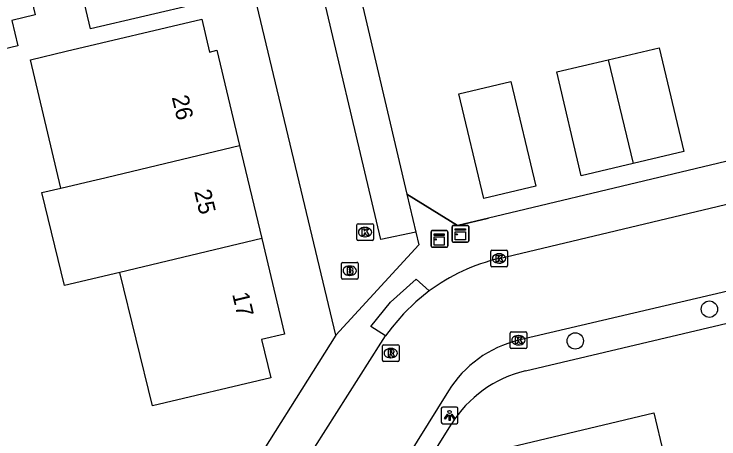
# Model space of a CAD drawing. Extents: x 158474 to 159560, y 388525 to 389605.
# Drawn here: x 159361.76 to 159403.9, y 388790.44 to 388815.87 of the extents above; entities that cross this region are included whole.
import ezdxf

# ---------------------------------------------------------------- set-up
doc = ezdxf.new("R2010")
doc.units = 0
for name, color, linetype in [('IMGEO_Boom', 7, 'Continuous'), ('IMGEO_Brandkraan', 7, 'Continuous'), ('IMGEO_Kast', 7, 'Continuous'), ('IMGEO_Kolk', 7, 'Continuous'), ('IMGEO_Lichtpunt', 7, 'Continuous'), ('IMGEO_Muur', 7, 'Continuous'), ('IMGEO_Pand', 7, 'Continuous'), ('IMGEO_Pand_nummerreeks', 7, 'Continuous'), ('IMGEO_Parkeervlak_open', 7, 'Continuous'), ('IMGEO_Rijbaan_lokaal_open', 7, 'Continuous'), ('IMGEO_Rioolput', 7, 'Continuous'), ('IMGEO_Voetpad_open', 7, 'Continuous')]:
    doc.layers.add(name, color=color, linetype=linetype)

msp = doc.modelspace()

# ---------------------------------------------------------------- linework, layer by layer
at = {"layer": 'IMGEO_Boom'}
for centre in [(159403.329, 388798.208), (159395.311, 388796.305)]:
    msp.add_circle(centre, 0.489, dxfattribs=at)
at = {"layer": 'IMGEO_Brandkraan'}
for p, q in [((159381.326, 388800.085), (159381.326, 388800.937)), ((159381.401, 388801.011), (159382.253, 388801.011)), ((159381.814, 388800.791), (159381.839, 388800.791)), ((159382.327, 388800.937), (159382.327, 388800.085)), ((159382.253, 388800.011), (159381.401, 388800.011)), ((159381.837, 388800.231), (159381.812, 388800.231))]:
    msp.add_line(p, q, dxfattribs=at)
for points in [[(159381.326, 388800.085), (159381.326, 388800.937)], [(159381.401, 388801.011), (159382.253, 388801.011)], [(159381.674, 388800.711), (159381.674, 388800.311), (159381.887, 388800.311)], [(159381.905, 388800.711), (159381.674, 388800.711)], [(159382.327, 388800.937), (159382.327, 388800.085)], [(159381.853, 388800.63), (159381.799, 388800.63), (159381.799, 388800.554)], [(159381.799, 388800.554), (159381.852, 388800.554)], [(159381.861, 388800.478), (159381.799, 388800.478), (159381.799, 388800.397)], [(159381.799, 388800.397), (159381.861, 388800.397)], [(159382.253, 388800.011), (159381.401, 388800.011)]]:
    msp.add_lwpolyline(points, dxfattribs=at)
for centre, radius, start, end in [((159381.403, 388800.935), 0.0765, 91.552, 178.448), ((159381.403, 388800.935), 0.0765, 91.552, 178.448), ((159381.909, 388800.566), 0.145, 59.4692, 91.5367), ((159382.251, 388800.935), 0.0765, 1.552, 88.448), ((159382.251, 388800.935), 0.0765, 1.552, 88.448), ((159381.854, 388800.592), 0.0379, 267.8285, 90.9355), ((159381.862, 388800.437), 0.0404, 269.8759, 90.5077), ((159381.893, 388800.562), 0.251, 268.6676, 293.5347), ((159381.934, 388800.613), 0.0922, 285.5137, 58.1501), ((159381.939, 388800.421), 0.105, 301.3115, 78.989), ((159381.403, 388800.087), 0.0765, 181.552, 268.448), ((159381.403, 388800.087), 0.0765, 181.552, 268.448), ((159382.251, 388800.087), 0.0765, 271.552, 358.448), ((159382.251, 388800.087), 0.0765, 271.552, 358.448)]:
    msp.add_arc(centre, radius, start, end, dxfattribs=at)
for centre, major_axis, ratio, start_param, end_param in [((159381.813, 388800.511), (-0.387, 0.002), 0.722429, 4.712389, 7.853982), ((159381.838, 388800.511), (-0.39, 0.002), 0.717154, 1.570796, 4.712389)]:
    msp.add_ellipse(centre, major_axis=major_axis, ratio=ratio, start_param=start_param, end_param=end_param, dxfattribs=at)
at = {"layer": 'IMGEO_Kast'}
for p, q in [((159388.02, 388803.222), (159388.861, 388803.222)), ((159388.861, 388803.222), (159388.02, 388803.222)), ((159386.687, 388801.995), (159386.687, 388802.836)), ((159386.687, 388802.836), (159386.687, 388801.995)), ((159386.762, 388802.92), (159387.603, 388802.92)), ((159387.603, 388802.92), (159386.762, 388802.92)), ((159387.687, 388802.845), (159387.687, 388802.004)), ((159387.687, 388802.004), (159387.687, 388802.845)), ((159387.945, 388802.297), (159387.945, 388803.138)), ((159387.945, 388803.138), (159387.945, 388802.297)), ((159388.945, 388803.147), (159388.945, 388802.306)), ((159388.945, 388802.306), (159388.945, 388803.147)), ((159388.87, 388802.222), (159388.029, 388802.222)), ((159388.029, 388802.222), (159388.87, 388802.222)), ((159387.612, 388801.92), (159386.771, 388801.92)), ((159386.771, 388801.92), (159387.612, 388801.92))]:
    msp.add_line(p, q, dxfattribs=at)
for points in [[(159388.14, 388803.012), (159388.74, 388803.012), (159388.74, 388802.927), (159388.14, 388802.927), (159388.14, 388803.012)], [(159388.14, 388802.837), (159388.74, 388802.837), (159388.74, 388802.348), (159388.14, 388802.348), (159388.14, 388802.837)], [(159386.882, 388802.71), (159387.482, 388802.71), (159387.482, 388802.625), (159386.882, 388802.625), (159386.882, 388802.71)], [(159386.882, 388802.535), (159387.482, 388802.535), (159387.482, 388802.046), (159386.882, 388802.046), (159386.882, 388802.535)]]:
    msp.add_lwpolyline(points, dxfattribs=at)
for centre in [(159386.966, 388802.384), (159388.224, 388802.686)]:
    msp.add_circle(centre, 0.0377, dxfattribs=at)
for centre, start, end in [((159388.023, 388803.144), 92.4484, 184.2845), ((159388.023, 388803.144), 92.4484, 184.2845), ((159388.867, 388803.144), 2.4484, 94.2845), ((159388.867, 388803.144), 2.4484, 94.2845), ((159386.765, 388802.842), 92.4484, 184.2845), ((159386.765, 388802.842), 92.4484, 184.2845), ((159387.609, 388802.842), 2.4484, 94.2845), ((159387.609, 388802.842), 2.4484, 94.2845), ((159386.765, 388801.998), 182.4484, 274.2845), ((159386.765, 388801.998), 182.4484, 274.2845), ((159387.609, 388801.998), 272.4484, 4.2845), ((159387.609, 388801.998), 272.4484, 4.2845), ((159388.023, 388802.3), 182.4484, 274.2845), ((159388.023, 388802.3), 182.4484, 274.2845), ((159388.867, 388802.3), 272.4484, 4.2845), ((159388.867, 388802.3), 272.4484, 4.2845)]:
    msp.add_arc(centre, 0.0779, start, end, dxfattribs=at)
at = {"layer": 'IMGEO_Kolk'}
for p, q in [((159382.247, 388802.397), (159382.247, 388803.249)), ((159382.322, 388803.323), (159383.174, 388803.323)), ((159383.248, 388803.249), (159383.248, 388802.397)), ((159382.735, 388803.103), (159382.76, 388803.103)), ((159382.758, 388802.543), (159382.733, 388802.543)), ((159383.174, 388802.323), (159382.322, 388802.323)), ((159390.257, 388800.815), (159390.257, 388801.667)), ((159390.332, 388801.741), (159391.184, 388801.741)), ((159391.258, 388801.667), (159391.258, 388800.815)), ((159390.745, 388801.521), (159390.77, 388801.521)), ((159391.184, 388800.741), (159390.332, 388800.741)), ((159390.768, 388800.961), (159390.743, 388800.961)), ((159391.412, 388795.919), (159391.412, 388796.771)), ((159391.487, 388796.845), (159392.339, 388796.845)), ((159391.9, 388796.625), (159391.925, 388796.625)), ((159392.413, 388796.771), (159392.413, 388795.919)), ((159391.923, 388796.065), (159391.898, 388796.065)), ((159392.339, 388795.845), (159391.487, 388795.845))]:
    msp.add_line(p, q, dxfattribs=at)
for points in [[(159382.247, 388802.397), (159382.247, 388803.249)], [(159382.322, 388803.323), (159383.174, 388803.323)], [(159383.248, 388803.249), (159383.248, 388802.397)], [(159382.568, 388803.023), (159382.691, 388803.023), (159382.691, 388802.872), (159382.821, 388803.023), (159382.985, 388803.023), (159382.839, 388802.872), (159382.992, 388802.623), (159382.84, 388802.623), (159382.755, 388802.787), (159382.691, 388802.72), (159382.691, 388802.623), (159382.568, 388802.623), (159382.568, 388803.023)], [(159383.174, 388802.323), (159382.322, 388802.323)], [(159390.257, 388800.815), (159390.257, 388801.667)], [(159390.332, 388801.741), (159391.184, 388801.741)], [(159391.258, 388801.667), (159391.258, 388800.815)], [(159390.578, 388801.441), (159390.701, 388801.441), (159390.701, 388801.29), (159390.831, 388801.441), (159390.995, 388801.441), (159390.849, 388801.29), (159391.002, 388801.041), (159390.85, 388801.041), (159390.765, 388801.205), (159390.701, 388801.138), (159390.701, 388801.041), (159390.578, 388801.041), (159390.578, 388801.441)], [(159391.184, 388800.741), (159390.332, 388800.741)], [(159391.412, 388795.919), (159391.412, 388796.771)], [(159391.487, 388796.845), (159392.339, 388796.845)], [(159391.733, 388796.545), (159391.856, 388796.545), (159391.856, 388796.394), (159391.986, 388796.545), (159392.15, 388796.545), (159392.004, 388796.394), (159392.157, 388796.145), (159392.005, 388796.145), (159391.92, 388796.309), (159391.856, 388796.242), (159391.856, 388796.145), (159391.733, 388796.145), (159391.733, 388796.545)], [(159392.413, 388796.771), (159392.413, 388795.919)], [(159392.339, 388795.845), (159391.487, 388795.845)]]:
    msp.add_lwpolyline(points, dxfattribs=at)
for centre, start, end in [((159382.324, 388803.247), 91.552, 178.448), ((159382.324, 388803.247), 91.552, 178.448), ((159383.172, 388803.247), 1.552, 88.448), ((159383.172, 388803.247), 1.552, 88.448), ((159382.324, 388802.399), 181.552, 268.448), ((159382.324, 388802.399), 181.552, 268.448), ((159383.172, 388802.399), 271.552, 358.448), ((159383.172, 388802.399), 271.552, 358.448), ((159390.334, 388801.665), 91.552, 178.448), ((159390.334, 388801.665), 91.552, 178.448), ((159391.182, 388801.665), 1.552, 88.448), ((159391.182, 388801.665), 1.552, 88.448), ((159390.334, 388800.817), 181.552, 268.448), ((159390.334, 388800.817), 181.552, 268.448), ((159391.182, 388800.817), 271.552, 358.448), ((159391.182, 388800.817), 271.552, 358.448), ((159391.489, 388796.769), 91.552, 178.448), ((159391.489, 388796.769), 91.552, 178.448), ((159392.337, 388796.769), 1.552, 88.448), ((159392.337, 388796.769), 1.552, 88.448), ((159391.489, 388795.921), 181.552, 268.448), ((159391.489, 388795.921), 181.552, 268.448), ((159392.337, 388795.921), 271.552, 358.448), ((159392.337, 388795.921), 271.552, 358.448)]:
    msp.add_arc(centre, 0.0765, start, end, dxfattribs=at)
for centre, major_axis, ratio, start_param, end_param in [((159382.734, 388802.823), (-0.387, 0.002), 0.722429, 4.712389, 7.853982), ((159382.759, 388802.823), (-0.39, 0.002), 0.717154, 1.570796, 4.712389), ((159390.744, 388801.241), (-0.387, 0.002), 0.722429, 4.712389, 7.853982), ((159390.769, 388801.241), (-0.39, 0.002), 0.717154, 1.570796, 4.712389), ((159391.899, 388796.345), (-0.387, 0.002), 0.722429, 4.712389, 7.853982), ((159391.924, 388796.345), (-0.39, 0.002), 0.717154, 1.570796, 4.712389)]:
    msp.add_ellipse(centre, major_axis=major_axis, ratio=ratio, start_param=start_param, end_param=end_param, dxfattribs=at)
at = {"layer": 'IMGEO_Lichtpunt'}
for p, q in [((159388.204, 388792.351), (159387.396, 388792.351)), ((159388.204, 388792.351), (159387.396, 388792.351)), ((159387.302, 388792.256), (159387.302, 388791.449)), ((159387.302, 388792.256), (159387.302, 388791.449)), ((159388.298, 388791.449), (159388.298, 388792.256)), ((159388.298, 388791.449), (159388.298, 388792.256)), ((159387.396, 388791.355), (159388.204, 388791.355)), ((159387.396, 388791.355), (159388.204, 388791.355))]:
    msp.add_line(p, q, dxfattribs=at)
for points in [[(159387.676, 388791.92), (159387.715, 388791.892), (159387.527, 388791.63), (159387.489, 388791.657), (159387.676, 388791.92)], [(159387.778, 388791.872), (159387.825, 388791.872), (159387.825, 388791.55), (159387.778, 388791.55), (159387.778, 388791.872)], [(159387.888, 388791.892), (159387.926, 388791.919), (159388.113, 388791.657), (159388.074, 388791.629), (159387.888, 388791.892)]]:
    msp.add_lwpolyline(points, dxfattribs=at)
msp.add_circle((159387.801, 388792.054), 0.0994, dxfattribs=at)
for centre, start, end in [((159387.396, 388792.256), 90, 180), ((159387.396, 388792.256), 90, 180), ((159388.204, 388792.256), 0, 90), ((159388.204, 388792.256), 0, 90), ((159387.396, 388791.449), 180, 270), ((159387.396, 388791.449), 180, 270), ((159388.204, 388791.449), 270, 0), ((159388.204, 388791.449), 270, 360)]:
    msp.add_arc(centre, 0.0946, start, end, dxfattribs=at)
at = {"layer": 'IMGEO_Muur'}
for points in [[(159379.972, 388822.547), (159380.507, 388820.264), (159381.615, 388820.579), (159385.247, 388805.085)], [(159385.247, 388805.085), (159388.275, 388803.211), (159390.115, 388803.651)]]:
    msp.add_lwpolyline(points, dxfattribs=at)
at = {"layer": 'IMGEO_Pand'}
for points in [[(159361.669, 388821.527), (159363.019, 388815.821), (159361.632, 388815.493), (159361.994, 388813.963), (159357.129, 388812.812), (159354.842, 388812.271), (159353.13, 388819.506)], [(159364.564, 388805.452), (159362.735, 388813.135), (159364.88, 388813.646), (159372.98, 388815.574), (159373.45, 388813.599), (159373.887, 388813.703), (159375.246, 388807.995)], [(159397.28, 388813.132), (159400.326, 388813.851), (159401.793, 388807.635), (159398.767, 388806.921)], [(159398.767, 388806.921), (159395.671, 388806.19), (159394.204, 388812.406), (159397.28, 388813.132)], [(159397.28, 388813.132), (159398.767, 388806.921)], [(159392.951, 388805.569), (159389.836, 388804.829), (159388.351, 388811.087), (159391.465, 388811.826), (159392.951, 388805.569)], [(159364.564, 388805.452), (159366.743, 388805.971), (159366.849, 388805.996), (159375.246, 388807.995)], [(159375.246, 388807.995), (159376.571, 388802.43)], [(159368.092, 388800.411), (159364.778, 388799.622), (159363.429, 388805.182), (159364.564, 388805.452)], [(159376.571, 388802.43), (159377.932, 388796.712), (159376.561, 388796.385), (159377.104, 388794.103), (159370.032, 388792.419), (159368.092, 388800.411)], [(159376.571, 388802.43), (159368.092, 388800.411)], [(159392.638, 388783.919), (159391.801, 388787.419), (159390.318, 388787.064), (159389.724, 388789.548), (159400.007, 388792.007), (159401.17, 388787.145), (159401.441, 388786.012)]]:
    msp.add_lwpolyline(points, dxfattribs=at)
at = {"layer": 'IMGEO_Parkeervlak_open'}
msp.add_lwpolyline([(159380.507, 388820.264), (159381.615, 388820.579), (159385.247, 388805.085)], dxfattribs=at)
at = {"layer": 'IMGEO_Rijbaan_lokaal_open'}
for points in [[(159381.001, 388796.659), (159376.084, 388817.274), (159366.321, 388814.977), (159361.595, 388835.064), (159357.461, 388833.992), (159357.277, 388833.944)], [(159385.776, 388802.823), (159383.685, 388802.38), (159379.531, 388820.032), (159380.507, 388820.264)], [(159390.761, 388801.243), (159424.747, 388809.352)], [(159425.935, 388804.377), (159418.221, 388802.518), (159391.91, 388796.343)], [(159385.776, 388802.823), (159385.956, 388802.054), (159381.001, 388796.659)], [(159386.576, 388799.296), (159385.773, 388798.645), (159385.032, 388797.924), (159384.358, 388797.14), (159383.973, 388796.62)], [(159379.09, 388788.918), (159383.682, 388796.182), (159383.973, 388796.62)], [(159387.725, 388793.314), (159383.331, 388786.236)]]:
    msp.add_lwpolyline(points, dxfattribs=at)
for centre, radius, start, end in [((159393.434, 388790.026), 11.531, 103.4041, 126.4947), ((159393.521, 388789.712), 6.824, 103.6534, 148.1388)]:
    msp.add_arc(centre, radius, start, end, dxfattribs=at)
at = {"layer": 'IMGEO_Rioolput'}
for p, q in [((159383.856, 388796.08), (159384.708, 388796.08)), ((159383.781, 388795.154), (159383.781, 388796.006)), ((159384.269, 388795.86), (159384.294, 388795.86)), ((159384.782, 388796.006), (159384.782, 388795.154)), ((159384.292, 388795.3), (159384.267, 388795.3)), ((159384.708, 388795.08), (159383.856, 388795.08))]:
    msp.add_line(p, q, dxfattribs=at)
for points in [[(159383.856, 388796.08), (159384.708, 388796.08)], [(159383.781, 388795.154), (159383.781, 388796.006)], [(159384.37, 388795.778), (159384.118, 388795.78), (159384.118, 388795.38)], [(159384.296, 388795.699), (159384.242, 388795.699), (159384.242, 388795.618)], [(159384.782, 388796.006), (159384.782, 388795.154)], [(159384.118, 388795.38), (159384.242, 388795.38), (159384.242, 388795.542), (159384.253, 388795.542)], [(159384.242, 388795.618), (159384.294, 388795.618)], [(159384.3, 388795.513), (159384.371, 388795.38), (159384.511, 388795.38), (159384.446, 388795.506)], [(159384.708, 388795.08), (159383.856, 388795.08)]]:
    msp.add_lwpolyline(points, dxfattribs=at)
for centre, radius, start, end in [((159383.858, 388796.004), 0.0765, 91.552, 178.448), ((159383.858, 388796.004), 0.0765, 91.552, 178.448), ((159384.706, 388796.004), 0.0765, 1.552, 88.448), ((159384.706, 388796.004), 0.0765, 1.552, 88.448), ((159384.302, 388795.603), 0.0964, 77.0061, 93.1865), ((159384.316, 388795.66), 0.0378, 276.6634, 79.6772), ((159384.369, 388795.668), 0.109, 350.3612, 89.416), ((159384.367, 388795.668), 0.112, 277.5842, 350.9817), ((159384.252, 388795.489), 0.0533, 26.0293, 88.6989), ((159384.278, 388795.807), 0.19, 274.7715, 282.9687), ((159384.351, 388795.453), 0.108, 29.5134, 73.7905), ((159383.858, 388795.156), 0.0765, 181.552, 268.448), ((159383.858, 388795.156), 0.0765, 181.552, 268.448), ((159384.706, 388795.156), 0.0765, 271.552, 358.448), ((159384.706, 388795.156), 0.0765, 271.552, 358.448)]:
    msp.add_arc(centre, radius, start, end, dxfattribs=at)
for centre, major_axis, ratio, start_param, end_param in [((159384.268, 388795.58), (-0.387, 0.002), 0.722429, 4.712389, 7.853982), ((159384.293, 388795.58), (-0.39, 0.002), 0.717154, 1.570796, 4.712389)]:
    msp.add_ellipse(centre, major_axis=major_axis, ratio=ratio, start_param=start_param, end_param=end_param, dxfattribs=at)
at = {"layer": 'IMGEO_Voetpad_open'}
for points in [[(159430.86, 388813.397), (159390.115, 388803.651), (159388.275, 388803.211), (159385.247, 388805.085)], [(159385.247, 388805.085), (159385.776, 388802.823)], [(159392.326, 388794.511), (159416.702, 388800.29)], [(159383.973, 388796.62), (159383.083, 388797.166), (159384.274, 388798.637), (159385.801, 388800.007), (159386.576, 388799.296)], [(159381.001, 388796.659), (159369, 388777.58), (159342.733, 388771.26), (159339.013, 388773.592), (159307.222, 388766.073)], [(159380.215, 388776.067), (159379.662, 388778.147), (159387.903, 388791.333)]]:
    msp.add_lwpolyline(points, dxfattribs=at)
msp.add_arc((159393.987, 388787.533), 7.173, 103.3867, 148.009, dxfattribs=at)

# ---------------------------------------------------------------- texts
at = {"layer": 'IMGEO_Pand_nummerreeks'}
for s, p in [('26', (159371.184, 388810.894)), ('25', (159372.526, 388805.257)), ('17', (159374.792, 388799.11))]:
    msp.add_text(s, height=1, rotation=283.3898, dxfattribs=at).set_placement(p)

doc.saveas('drawing.dxf')
